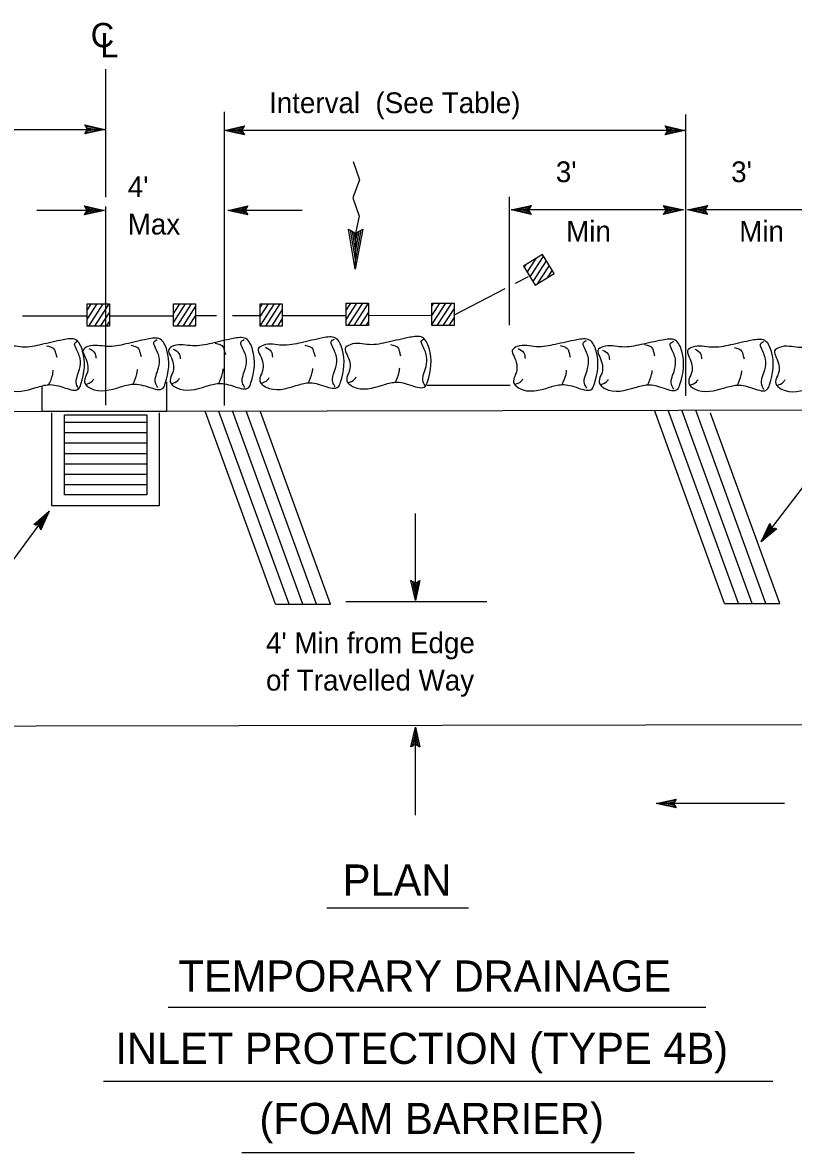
# Model space of a CAD drawing. Extents: x 6708945 to 6710368, y 1871409 to 1872338.
# Drawn here: x 6709691.9 to 6709914.8, y 1871409.2 to 1871735.8 of the extents above; entities that cross this region are included whole.
import ezdxf

# ---------------------------------------------------------------- set-up
doc = ezdxf.new("R2010")
doc.units = 0
for name, color, linetype in [('1 Control', 7, 'Continuous'), ('57 Undefined', 7, 'Continuous'), ('60 Nongeo Data', 7, 'Continuous'), ('63 Undefined', 7, 'Continuous')]:
    doc.layers.add(name, color=color, linetype=linetype)

msp = doc.modelspace()

# ---------------------------------------------------------------- linework, layer by layer
at = {"layer": '1 Control'}
for p, q in [((6709840.28, 1871667.52), (6709837.77, 1871663.66)), ((6709842.49, 1871668.29), (6709838.6, 1871662.29)), ((6709837.44, 1871665.8), (6709836.94, 1871665.03)), ((6709843.32, 1871666.92), (6709839.43, 1871660.93)), ((6709844.15, 1871665.55), (6709840.71, 1871660.25)), ((6709844.98, 1871664.19), (6709843.54, 1871661.97)), ((6709713.36, 1871654.41), (6709710.54, 1871650.07)), ((6709711.64, 1871654.41), (6709710.54, 1871652.71)), ((6709715.08, 1871654.41), (6709710.89, 1871647.97)), ((6709716.79, 1871654.41), (6709712.61, 1871647.97)), ((6709738.92, 1871654.41), (6709735.48, 1871649.11)), ((6709737.2, 1871654.41), (6709735.48, 1871651.75)), ((6709735.49, 1871654.41), (6709735.48, 1871654.39)), ((6709740.64, 1871654.41), (6709736.46, 1871647.97)), ((6709764.57, 1871654.41), (6709760.53, 1871648.19)), ((6709762.85, 1871654.41), (6709760.53, 1871650.84)), ((6709761.13, 1871654.41), (6709760.53, 1871653.48)), ((6709766.28, 1871654.41), (6709762.1, 1871647.97)), ((6709788.42, 1871654.6), (6709785.47, 1871650.05)), ((6709786.7, 1871654.6), (6709785.47, 1871652.7)), ((6709790.14, 1871654.6), (6709785.96, 1871648.16)), ((6709791.85, 1871654.6), (6709787.67, 1871648.16)), ((6709814.16, 1871654.6), (6709810.22, 1871648.53)), ((6709812.44, 1871654.6), (6709810.22, 1871651.17)), ((6709810.73, 1871654.6), (6709810.22, 1871653.82)), ((6709815.88, 1871654.6), (6709811.7, 1871648.16)), ((6709716.98, 1871652.05), (6709714.33, 1871647.97)), ((6709741.91, 1871653.73), (6709738.17, 1871647.97)), ((6709741.91, 1871651.08), (6709739.89, 1871647.97)), ((6709766.97, 1871652.82), (6709763.82, 1871647.97)), ((6709791.9, 1871652.03), (6709789.39, 1871648.16)), ((6709816.65, 1871653.15), (6709813.41, 1871648.16)), ((6709716.98, 1871649.4), (6709716.05, 1871647.97)), ((6709741.91, 1871648.44), (6709741.61, 1871647.97)), ((6709766.97, 1871650.17), (6709765.54, 1871647.97)), ((6709791.9, 1871649.39), (6709791.11, 1871648.16)), ((6709816.65, 1871650.51), (6709815.13, 1871648.16))]:
    msp.add_line(p, q, dxfattribs=at)
for points in [[(6709842.23, 1871668.71), (6709836.73, 1871665.37), (6709840.07, 1871659.87), (6709845.57, 1871663.2)], [(6709710.54, 1871654.41), (6709716.98, 1871654.41), (6709716.98, 1871647.97), (6709710.54, 1871647.97)], [(6709735.48, 1871654.41), (6709741.91, 1871654.41), (6709741.91, 1871647.97), (6709735.48, 1871647.97)], [(6709760.53, 1871654.41), (6709766.97, 1871654.41), (6709766.97, 1871647.97), (6709760.53, 1871647.97)], [(6709785.47, 1871654.6), (6709791.9, 1871654.6), (6709791.9, 1871648.16), (6709785.47, 1871648.16)], [(6709810.22, 1871654.6), (6709816.65, 1871654.6), (6709816.65, 1871648.16), (6709810.22, 1871648.16)]]:
    msp.add_lwpolyline(points, close=True, dxfattribs=at)
at = {"layer": '57 Undefined'}
for p, q in [((6709715.85, 1871722.28), (6709715.85, 1871685.32)), ((6709750.26, 1871625.05), (6709750.26, 1871709.96)), ((6709883.68, 1871627.81), (6709883.68, 1871709.2)), ((6709588.34, 1871704.86), (6709715.63, 1871704.86)), ((6709883.41, 1871704.6), (6709750.29, 1871704.6)), ((6709832.72, 1871648.29), (6709832.72, 1871685.42)), ((6709715.55, 1871681.47), (6709696, 1871681.47)), ((6709715.85, 1871682.57), (6709715.85, 1871625.12)), ((6709772.68, 1871681.47), (6709751.21, 1871681.47)), ((6709883.02, 1871681.58), (6709833.18, 1871681.58)), ((6709934.78, 1871681.58), (6709884.17, 1871681.58)), ((6709905.48, 1871585.64), (6709978.12, 1871680.81)), ((6709668.01, 1871551.82), (6709699.53, 1871594.51)), ((6709805.46, 1871568.74), (6709805.46, 1871593.84)), ((6709826.16, 1871568.32), (6709785.33, 1871568.32)), ((6709805.46, 1871506.6), (6709805.46, 1871532.11)), ((6709912.24, 1871510.02), (6709875.09, 1871510.02)), ((6709779.84, 1871479.86), (6709820.79, 1871479.86)), ((6709733.95, 1871451.17), (6709889.47, 1871451.17)), ((6709715.26, 1871429.73), (6709908.83, 1871429.73)), ((6709755.31, 1871409.15), (6709868.78, 1871409.15))]:
    msp.add_line(p, q, dxfattribs=at)
at = {"layer": '60 Nongeo Data'}
for p, q in [((6709709.87, 1871706.15), (6709709.87, 1871706.15)), ((6709709.87, 1871703.59), (6709709.87, 1871703.59)), ((6709715.63, 1871704.86), (6709715.63, 1871704.86)), ((6709750.29, 1871704.6), (6709750.29, 1871704.6)), ((6709756.05, 1871705.87), (6709756.05, 1871705.87)), ((6709756.05, 1871703.31), (6709756.05, 1871703.31)), ((6709877.65, 1871705.88), (6709877.65, 1871705.88)), ((6709877.65, 1871703.32), (6709877.65, 1871703.32)), ((6709883.41, 1871704.6), (6709883.41, 1871704.6)), ((6709709.8, 1871682.75), (6709709.8, 1871682.75)), ((6709715.55, 1871681.47), (6709715.55, 1871681.47)), ((6709751.21, 1871681.47), (6709751.21, 1871681.47)), ((6709756.97, 1871682.74), (6709756.97, 1871682.74)), ((6709833.18, 1871681.58), (6709833.18, 1871681.58)), ((6709838.94, 1871682.86), (6709838.94, 1871682.86)), ((6709877.26, 1871682.87), (6709877.26, 1871682.87)), ((6709883.02, 1871681.58), (6709883.02, 1871681.58)), ((6709884.17, 1871681.58), (6709884.17, 1871681.58)), ((6709889.93, 1871682.86), (6709889.93, 1871682.86)), ((6709709.8, 1871680.19), (6709709.8, 1871680.19)), ((6709756.97, 1871680.18), (6709756.97, 1871680.18)), ((6709838.94, 1871680.29), (6709838.94, 1871680.29)), ((6709877.26, 1871680.3), (6709877.26, 1871680.3)), ((6709889.93, 1871680.29), (6709889.93, 1871680.29)), ((6709764.96, 1871567.62), (6709744.67, 1871623.38)), ((6709768.94, 1871567.63), (6709748.65, 1871623.37)), ((6709772.92, 1871567.63), (6709752.57, 1871623.56)), ((6709776.9, 1871567.64), (6709756.55, 1871623.56)), ((6709780.89, 1871567.65), (6709760.64, 1871623.27)), ((6709894.89, 1871567.85), (6709874.57, 1871623.68)), ((6709898.88, 1871567.83), (6709878.55, 1871623.69)), ((6709902.87, 1871567.83), (6709882.54, 1871623.69)), ((6709906.85, 1871567.83), (6709886.52, 1871623.7)), ((6709910.82, 1871567.87), (6709890.82, 1871622.81)), ((6709704.01, 1871620.22), (6709727.8, 1871620.22)), ((6709704.01, 1871617.22), (6709727.8, 1871617.22)), ((6709704.01, 1871614.23), (6709727.8, 1871614.23)), ((6709704.01, 1871611.23), (6709727.8, 1871611.23)), ((6709704.01, 1871608.24), (6709727.8, 1871608.24)), ((6709704.01, 1871605.24), (6709727.8, 1871605.24)), ((6709704.01, 1871602.25), (6709727.8, 1871602.25)), ((6709699.53, 1871594.51), (6709699.53, 1871594.51)), ((6709695.07, 1871590.64), (6709695.07, 1871590.64)), ((6709697.13, 1871589.12), (6709697.13, 1871589.12)), ((6709907.96, 1871590.99), (6709907.96, 1871590.99)), ((6709909.99, 1871589.43), (6709909.99, 1871589.43)), ((6709905.48, 1871585.64), (6709905.48, 1871585.64)), ((6709804.19, 1871574.5), (6709804.19, 1871574.5)), ((6709806.75, 1871574.5), (6709806.75, 1871574.5)), ((6709805.46, 1871568.74), (6709805.46, 1871568.74)), ((6709805.46, 1871532.11), (6709805.46, 1871532.11)), ((6709804.18, 1871526.35), (6709804.18, 1871526.35)), ((6709806.74, 1871526.35), (6709806.74, 1871526.35)), ((6709880.85, 1871511.29), (6709880.85, 1871511.29)), ((6709875.09, 1871510.02), (6709875.09, 1871510.02)), ((6709880.85, 1871508.73), (6709880.85, 1871508.73))]:
    msp.add_line(p, q, dxfattribs=at)
for points in [[(6709709.87, 1871706.15), (6709715.63, 1871704.86), (6709709.87, 1871703.59), (6709710.08, 1871703.93), (6709714.3, 1871704.86), (6709710.08, 1871705.81), (6709710.28, 1871705.47), (6709712.98, 1871704.87), (6709710.28, 1871704.27), (6709710.49, 1871704.61), (6709711.65, 1871704.87), (6709710.48, 1871705.13), (6709710.64, 1871704.86), (6709709.87, 1871703.59), (6709710.64, 1871704.86)], [(6709756.05, 1871703.31), (6709750.29, 1871704.6), (6709756.05, 1871705.87), (6709755.85, 1871705.53), (6709751.63, 1871704.6), (6709755.85, 1871703.65), (6709755.64, 1871703.99), (6709752.94, 1871704.59), (6709755.64, 1871705.19), (6709755.44, 1871704.85), (6709754.27, 1871704.59), (6709755.44, 1871704.33), (6709755.28, 1871704.6), (6709756.05, 1871705.87), (6709755.28, 1871704.6)], [(6709877.65, 1871705.88), (6709883.41, 1871704.6), (6709877.65, 1871703.32), (6709877.85, 1871703.66), (6709882.07, 1871704.59), (6709877.85, 1871705.54), (6709878.05, 1871705.2), (6709880.75, 1871704.6), (6709878.05, 1871704), (6709878.26, 1871704.34), (6709879.43, 1871704.6), (6709878.26, 1871704.86), (6709878.41, 1871704.6), (6709877.65, 1871703.32), (6709878.41, 1871704.6)], [(6709709.8, 1871682.75), (6709715.55, 1871681.47), (6709709.79, 1871680.19), (6709710, 1871680.53), (6709714.22, 1871681.46), (6709710, 1871682.41), (6709710.2, 1871682.07), (6709712.9, 1871681.47), (6709710.2, 1871680.87), (6709710.41, 1871681.21), (6709711.58, 1871681.47), (6709710.41, 1871681.73), (6709710.56, 1871681.47), (6709709.79, 1871680.19), (6709710.56, 1871681.47)], [(6709756.97, 1871680.18), (6709751.21, 1871681.47), (6709756.97, 1871682.74), (6709756.77, 1871682.4), (6709752.55, 1871681.47), (6709756.77, 1871680.52), (6709756.56, 1871680.86), (6709753.86, 1871681.47), (6709756.56, 1871682.06), (6709756.36, 1871681.72), (6709755.19, 1871681.46), (6709756.36, 1871681.2), (6709756.2, 1871681.47), (6709756.97, 1871682.74), (6709756.2, 1871681.47)], [(6709838.94, 1871680.29), (6709833.18, 1871681.58), (6709838.94, 1871682.86), (6709838.74, 1871682.52), (6709834.52, 1871681.58), (6709838.74, 1871680.64), (6709838.53, 1871680.98), (6709835.83, 1871681.58), (6709838.53, 1871682.18), (6709838.33, 1871681.84), (6709837.16, 1871681.58), (6709838.33, 1871681.32), (6709838.17, 1871681.58), (6709838.94, 1871682.86), (6709838.17, 1871681.58)], [(6709877.26, 1871682.87), (6709883.02, 1871681.58), (6709877.26, 1871680.3), (6709877.47, 1871680.64), (6709881.69, 1871681.58), (6709877.47, 1871682.53), (6709877.67, 1871682.19), (6709880.37, 1871681.58), (6709877.67, 1871680.99), (6709877.88, 1871681.33), (6709879.04, 1871681.58), (6709877.87, 1871681.85), (6709878.03, 1871681.58), (6709877.26, 1871680.3), (6709878.03, 1871681.58)], [(6709889.93, 1871680.29), (6709884.17, 1871681.58), (6709889.93, 1871682.86), (6709889.73, 1871682.52), (6709885.51, 1871681.58), (6709889.73, 1871680.64), (6709889.53, 1871680.98), (6709886.82, 1871681.58), (6709889.52, 1871682.18), (6709889.32, 1871681.84), (6709888.15, 1871681.58), (6709889.32, 1871681.32), (6709889.16, 1871681.58), (6709889.93, 1871682.86), (6709889.16, 1871681.58)], [(6709704.01, 1871622.39), (6709727.8, 1871622.39), (6709727.8, 1871599.26), (6709704.01, 1871599.26)], [(6709695.07, 1871590.64), (6709699.53, 1871594.51), (6709697.13, 1871589.12), (6709696.98, 1871589.49), (6709698.74, 1871593.44), (6709695.47, 1871590.6), (6709695.86, 1871590.57), (6709697.95, 1871592.38), (6709696.83, 1871589.85), (6709696.68, 1871590.22), (6709697.16, 1871591.31), (6709696.26, 1871590.53), (6709696.56, 1871590.5), (6709697.13, 1871589.12), (6709696.56, 1871590.5)], [(6709909.99, 1871589.43), (6709905.48, 1871585.64), (6709907.96, 1871590.99), (6709908.1, 1871590.62), (6709906.28, 1871586.7), (6709909.6, 1871589.48), (6709909.2, 1871589.52), (6709907.09, 1871587.74), (6709908.25, 1871590.25), (6709908.39, 1871589.88), (6709907.89, 1871588.8), (6709908.81, 1871589.57), (6709908.5, 1871589.6), (6709907.96, 1871590.99), (6709908.5, 1871589.6)], [(6709806.75, 1871574.5), (6709805.46, 1871568.74), (6709804.19, 1871574.5), (6709804.53, 1871574.29), (6709805.46, 1871570.07), (6709806.41, 1871574.29), (6709806.07, 1871574.09), (6709805.47, 1871571.39), (6709804.87, 1871574.09), (6709805.21, 1871573.88), (6709805.47, 1871572.72), (6709805.73, 1871573.89), (6709805.46, 1871573.73), (6709804.19, 1871574.5), (6709805.46, 1871573.73)], [(6709804.18, 1871526.35), (6709805.46, 1871532.11), (6709806.74, 1871526.35), (6709806.4, 1871526.55), (6709805.47, 1871530.77), (6709804.52, 1871526.55), (6709804.86, 1871526.75), (6709805.46, 1871529.46), (6709806.06, 1871526.76), (6709805.72, 1871526.96), (6709805.46, 1871528.13), (6709805.2, 1871526.96), (6709805.46, 1871527.12), (6709806.74, 1871526.35), (6709805.46, 1871527.12)], [(6709880.85, 1871508.73), (6709875.09, 1871510.02), (6709880.85, 1871511.29), (6709880.65, 1871510.95), (6709876.43, 1871510.02), (6709880.65, 1871509.07), (6709880.44, 1871509.41), (6709877.74, 1871510.01), (6709880.44, 1871510.61), (6709880.24, 1871510.27), (6709879.07, 1871510.01), (6709880.24, 1871509.75), (6709880.08, 1871510.02), (6709880.85, 1871511.29), (6709880.08, 1871510.02)]]:
    msp.add_lwpolyline(points, close=True, dxfattribs=at)
for points in [[(6709834.39, 1871660.45), (6709838.15, 1871662.4)], [(6709816.54, 1871651.16), (6709831.45, 1871658.92)], [(6709716.99, 1871651), (6709735.4, 1871651.03)], [(6709742.03, 1871651.04), (6709747.94, 1871651.05)], [(6709752.53, 1871651.06), (6709760.39, 1871651.07)], [(6709767.14, 1871651.08), (6709785.43, 1871651.11)], [(6709791.92, 1871651.12), (6709809.92, 1871651.15)], [(6709691.87, 1871650.96), (6709710.37, 1871650.99)], [(6709697.4, 1871630.53), (6709697.4, 1871623.44), (6709733.57, 1871623.44), (6709733.57, 1871631.87)], [(6709808.89, 1871630.92), (6709832.88, 1871630.96)], [(6709678.2, 1871623.36), (6709932.4, 1871623.77)], [(6709700.23, 1871622.97), (6709700.23, 1871596.11), (6709731.47, 1871596.11), (6709731.47, 1871622.97)], [(6709764.96, 1871567.62), (6709780.89, 1871567.65)], [(6709894.89, 1871567.85), (6709910.82, 1871567.87)], [(6709578.14, 1871532.3), (6710048.25, 1871533.08)]]:
    msp.add_lwpolyline(points, dxfattribs=at)
for points in [[(6709685.81, 1871633.55), (6709685.41, 1871631.49), (6709687.07, 1871629.88), (6709695.81, 1871630.27), (6709699.39, 1871631.08), (6709704.17, 1871630.12), (6709708.12, 1871629.94), (6709708.74, 1871631.23), (6709709.2, 1871640.9), (6709707.25, 1871644.03), (6709703.6, 1871644.06), (6709697.36, 1871642.67), (6709691.88, 1871641.95), (6709686.33, 1871641.92), (6709684.96, 1871640.86), (6709685.47, 1871639.03), (6709686.2, 1871634.53), (6709685.73, 1871633.32)], [(6709710.2, 1871633.73), (6709709.8, 1871631.68), (6709711.46, 1871630.07), (6709720.2, 1871630.45), (6709723.78, 1871631.26), (6709728.56, 1871630.31), (6709732.51, 1871630.12), (6709733.13, 1871631.41), (6709733.59, 1871641.08), (6709731.64, 1871644.22), (6709727.99, 1871644.25), (6709721.75, 1871642.85), (6709716.27, 1871642.13), (6709710.72, 1871642.1), (6709709.35, 1871641.05), (6709709.86, 1871639.21), (6709710.59, 1871634.72), (6709710.12, 1871633.5)], [(6709734.97, 1871633.91), (6709734.57, 1871631.86), (6709736.23, 1871630.25), (6709744.97, 1871630.63), (6709748.55, 1871631.44), (6709753.33, 1871630.49), (6709757.28, 1871630.3), (6709757.9, 1871631.59), (6709758.36, 1871641.26), (6709756.41, 1871644.4), (6709752.76, 1871644.43), (6709746.52, 1871643.03), (6709741.04, 1871642.31), (6709735.49, 1871642.28), (6709734.12, 1871641.23), (6709734.63, 1871639.4), (6709735.36, 1871634.9), (6709734.89, 1871633.68)], [(6709760.88, 1871634.08), (6709760.49, 1871632.03), (6709762.15, 1871630.42), (6709770.89, 1871630.8), (6709774.47, 1871631.61), (6709779.25, 1871630.66), (6709783.2, 1871630.48), (6709783.81, 1871631.77), (6709784.27, 1871641.43), (6709782.32, 1871644.57), (6709778.67, 1871644.6), (6709772.43, 1871643.2), (6709766.95, 1871642.48), (6709761.41, 1871642.45), (6709760.03, 1871641.4), (6709760.55, 1871639.57), (6709761.27, 1871635.07), (6709760.81, 1871633.85)], [(6709786.04, 1871634.26), (6709785.64, 1871632.21), (6709787.3, 1871630.6), (6709796.04, 1871630.98), (6709799.62, 1871631.79), (6709804.4, 1871630.84), (6709808.35, 1871630.65), (6709808.96, 1871631.94), (6709809.42, 1871641.61), (6709807.47, 1871644.75), (6709803.83, 1871644.77), (6709797.58, 1871643.38), (6709792.11, 1871642.66), (6709786.56, 1871642.63), (6709785.18, 1871641.58), (6709785.7, 1871639.74), (6709786.42, 1871635.25), (6709785.96, 1871634.03)], [(6709834.27, 1871633.71), (6709833.86, 1871631.67), (6709835.5, 1871630.04), (6709844.24, 1871630.34), (6709847.83, 1871631.11), (6709852.6, 1871630.11), (6709856.55, 1871629.89), (6709857.18, 1871631.17), (6709857.73, 1871640.83), (6709855.81, 1871643.99), (6709852.17, 1871644.05), (6709845.91, 1871642.72), (6709840.43, 1871642.06), (6709834.88, 1871642.08), (6709833.49, 1871641.04), (6709833.99, 1871639.2), (6709834.67, 1871634.7), (6709834.19, 1871633.49)], [(6709698.8, 1871642.35), (6709701.07, 1871641.19), (6709701.37, 1871640.27), (6709701.74, 1871639.05)], [(6709708.12, 1871629.86), (6709707.45, 1871631.24), (6709708.32, 1871635.57), (6709708.49, 1871638.62), (6709707.15, 1871641.98), (6709706.93, 1871642.89), (6709707.93, 1871643.72)], [(6709711.03, 1871641.56), (6709712.69, 1871640.33), (6709713.06, 1871638.73)], [(6709723.19, 1871642.53), (6709725.46, 1871641.37), (6709725.76, 1871640.46), (6709726.13, 1871639.24)], [(6709730.99, 1871630.25), (6709730.31, 1871631.63), (6709731.19, 1871635.96), (6709731.36, 1871639), (6709730.02, 1871642.36), (6709729.8, 1871643.28), (6709730.79, 1871644.11)], [(6709735.41, 1871641.37), (6709737.08, 1871640.14), (6709737.44, 1871638.54)], [(6709747.59, 1871643.1), (6709749.86, 1871641.94), (6709750.15, 1871641.02), (6709750.52, 1871639.8)], [(6709756.14, 1871630.24), (6709755.46, 1871631.61), (6709756.34, 1871635.95), (6709756.51, 1871638.99), (6709755.17, 1871642.35), (6709754.95, 1871643.27), (6709755.94, 1871644.1)], [(6709762.09, 1871641.91), (6709763.75, 1871640.68), (6709764.12, 1871639.08)], [(6709773.49, 1871642.51), (6709775.76, 1871641.35), (6709776.06, 1871640.43), (6709776.43, 1871639.21)], [(6709782.24, 1871630.41), (6709781.57, 1871631.78), (6709782.44, 1871636.12), (6709782.62, 1871639.16), (6709781.28, 1871642.52), (6709781.06, 1871643.44), (6709782.05, 1871644.27)], [(6709798.26, 1871642.69), (6709800.53, 1871641.53), (6709800.83, 1871640.61), (6709801.2, 1871639.39)], [(6709808.35, 1871630.58), (6709807.67, 1871631.95), (6709808.54, 1871636.29), (6709808.72, 1871639.33), (6709807.38, 1871642.69), (6709807.16, 1871643.61), (6709808.15, 1871644.44)], [(6709835.18, 1871641.54), (6709836.83, 1871640.29), (6709837.18, 1871638.69)], [(6709847.35, 1871642.39), (6709849.61, 1871641.21), (6709849.9, 1871640.29), (6709850.26, 1871639.06)], [(6709855.03, 1871630.03), (6709854.37, 1871631.41), (6709855.28, 1871635.74), (6709855.49, 1871638.78), (6709854.18, 1871642.15), (6709853.97, 1871643.07), (6709854.97, 1871643.89)], [(6709859.04, 1871633.65), (6709858.63, 1871631.6), (6709860.27, 1871629.97), (6709869.02, 1871630.27), (6709872.6, 1871631.05), (6709877.37, 1871630.05), (6709881.32, 1871629.82), (6709881.95, 1871631.11), (6709882.5, 1871640.77), (6709880.58, 1871643.93), (6709876.94, 1871643.99), (6709870.68, 1871642.66), (6709865.2, 1871641.99), (6709859.65, 1871642.02), (6709858.26, 1871640.98), (6709858.76, 1871639.14), (6709859.44, 1871634.63), (6709858.96, 1871633.42)], [(6709871.75, 1871642.71), (6709874.01, 1871641.53), (6709874.3, 1871640.61), (6709874.65, 1871639.39)], [(6709880.18, 1871629.77), (6709879.52, 1871631.15), (6709880.43, 1871635.48), (6709880.64, 1871638.52), (6709879.33, 1871641.89), (6709879.12, 1871642.81), (6709880.12, 1871643.63)], [(6709884.96, 1871633.57), (6709884.54, 1871631.52), (6709886.19, 1871629.89), (6709894.93, 1871630.19), (6709898.52, 1871630.96), (6709903.29, 1871629.96), (6709907.23, 1871629.74), (6709907.86, 1871631.02), (6709908.42, 1871640.69), (6709906.5, 1871643.84), (6709902.85, 1871643.91), (6709896.6, 1871642.57), (6709891.11, 1871641.91), (6709885.57, 1871641.93), (6709884.18, 1871640.89), (6709884.68, 1871639.05), (6709885.36, 1871634.55), (6709884.88, 1871633.34)], [(6709886.24, 1871641.39), (6709887.89, 1871640.14), (6709888.25, 1871638.53)], [(6709897.65, 1871641.87), (6709899.91, 1871640.69), (6709900.2, 1871639.77), (6709900.55, 1871638.54)], [(6709906.28, 1871629.68), (6709905.62, 1871631.06), (6709906.53, 1871635.39), (6709906.74, 1871638.43), (6709905.43, 1871641.8), (6709905.22, 1871642.72), (6709906.22, 1871643.54)], [(6709910.11, 1871633.5), (6709909.69, 1871631.45), (6709911.34, 1871629.82), (6709920.08, 1871630.12), (6709923.67, 1871630.89), (6709928.44, 1871629.89), (6709932.39, 1871629.67), (6709933.02, 1871630.95), (6709933.57, 1871640.61), (6709931.65, 1871643.77), (6709928, 1871643.84), (6709921.75, 1871642.5), (6709916.26, 1871641.84), (6709910.72, 1871641.86), (6709909.33, 1871640.82), (6709909.83, 1871638.98), (6709910.51, 1871634.48), (6709910.03, 1871633.27)], [(6709859.56, 1871641.1), (6709861.21, 1871639.86), (6709861.56, 1871638.25)], [(6709699.39, 1871631), (6709700.56, 1871634.04), (6709700.72, 1871635.25)], [(6709723.78, 1871631.18), (6709724.94, 1871634.22), (6709725.11, 1871635.44)], [(6709748.55, 1871631.36), (6709749.72, 1871634.4), (6709749.88, 1871635.62)], [(6709774.46, 1871631.54), (6709775.63, 1871634.57), (6709775.79, 1871635.79)], [(6709799.62, 1871631.71), (6709800.78, 1871634.75), (6709800.94, 1871635.97)], [(6709847.83, 1871631.03), (6709849.02, 1871634.06), (6709849.2, 1871635.27)], [(6709872.6, 1871630.97), (6709873.79, 1871634), (6709873.97, 1871635.21)], [(6709898.51, 1871630.89), (6709899.71, 1871633.91), (6709899.88, 1871635.13)], [(6709710.03, 1871631.14), (6709712.01, 1871632.12), (6709712.47, 1871632.8)], [(6709734.8, 1871631.32), (6709736.78, 1871632.3), (6709737.24, 1871632.98)], [(6709760.71, 1871631.49), (6709762.69, 1871632.47), (6709763.16, 1871633.15)], [(6709785.86, 1871631.67), (6709787.85, 1871632.65), (6709788.31, 1871633.33)], [(6709834.08, 1871631.13), (6709836.07, 1871632.08), (6709836.54, 1871632.76)], [(6709858.85, 1871631.07), (6709860.84, 1871632.02), (6709861.31, 1871632.7)], [(6709884.76, 1871630.98), (6709886.75, 1871631.94), (6709887.22, 1871632.61)], [(6709909.91, 1871630.91), (6709911.91, 1871631.86), (6709912.37, 1871632.54)]]:
    msp.add_spline(points, degree=3, dxfattribs=at)
at = {"layer": '63 Undefined'}
for p, q in [((6709788.09, 1871664.49), (6709786.15, 1871676.05)), ((6709786.15, 1871676.05), (6709788.18, 1871674.85)), ((6709788.11, 1871667.25), (6709786.69, 1871675.73)), ((6709788.14, 1871669.99), (6709787.23, 1871675.4)), ((6709788.16, 1871672.79), (6709787.78, 1871675.08)), ((6709790.23, 1871676.01), (6709788.09, 1871664.49)), ((6709789.69, 1871675.7), (6709788.11, 1871667.25)), ((6709789.14, 1871675.39), (6709788.14, 1871669.99)), ((6709788.59, 1871675.07), (6709788.16, 1871672.79)), ((6709788.18, 1871674.85), (6709790.23, 1871676.01))]:
    msp.add_line(p, q, dxfattribs=at)
msp.add_lwpolyline([(6709787.42, 1871695.63), (6709789.27, 1871690.32), (6709787.32, 1871685.06), (6709789.18, 1871679.76), (6709788.18, 1871674.85), (6709788.09, 1871664.49)], dxfattribs=at)

# ---------------------------------------------------------------- texts
at = {"layer": '57 Undefined'}
for s, height, p in [('C', 7.02, (6709711.56, 1871728.63)), ('L', 7.02, (6709714.33, 1871725.75)), ('Interval  (See Table)', 6, (6709763.15, 1871709.57)), ("3'", 6, (6709846.08, 1871689.62)), ("3'", 6, (6709896.79, 1871689.62)), ("4'", 6, (6709722.28, 1871685.29)), ('Max', 6, (6709722.28, 1871674.49)), ('Min', 6, (6709849.07, 1871672.44)), ('Min', 6, (6709899.12, 1871672.44)), ("4' Min from Edge ", 6, (6709762.25, 1871553.46)), ('of Travelled Way', 6, (6709762.25, 1871542.66)), ('PLAN', 9, (6709784.45, 1871483.38)), ('TEMPORARY DRAINAGE', 9, (6709736.95, 1871455.65)), ('INLET PROTECTION (TYPE 4B)', 9, (6709718.68, 1871434.73)), ('(FOAM BARRIER)', 9, (6709760.36, 1871414.47))]:
    msp.add_text(s, height=height, dxfattribs=at).set_placement(p)

doc.saveas('drawing.dxf')
